// Mitsubishi GX Works2 project: L系列PLC与BD45XX通信例程20170617   PLC: L02

PROGRAM MAIN
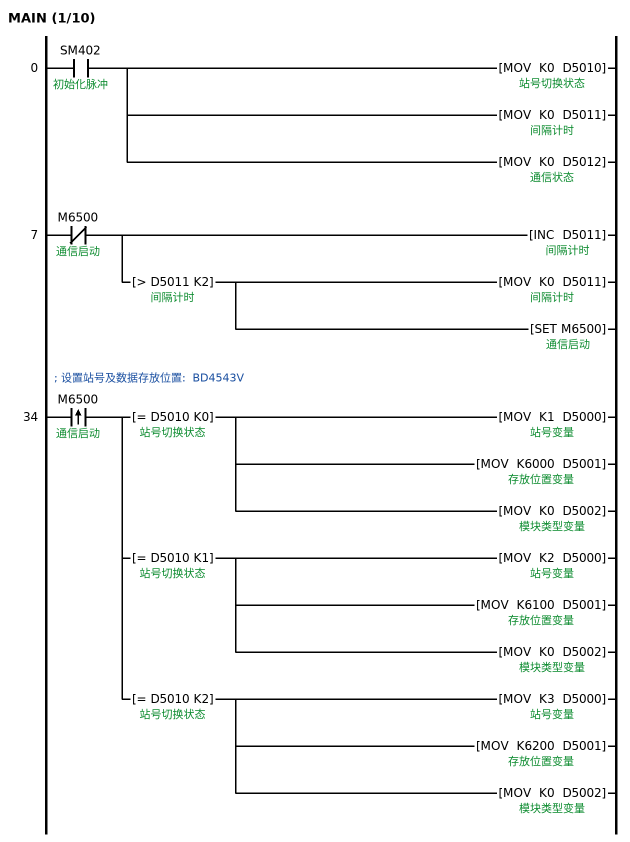
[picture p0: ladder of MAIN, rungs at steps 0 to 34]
0     LD      SM402  ; 初始化脉冲
      MOV     K0 D5010  ; 站号切换状态
      MOV     K0 D5011  ; 间隔计时
      MOV     K0 D5012  ; 通信状态
7     LDI     M6500  ; 通信启动
      INC     D5011
      AND>    D5011 K2  ; 间隔计时
      MOV     K0 D5011
      SET     M6500  ; 通信启动
; 设置站号及数据存放位置:  BD4543V
34    LDP     M6500  ; 通信启动
      MPS
      AND=    D5010 K0  ; 站号切换状态
      MOV     K1 D5000  ; 站号变量
      MOV     K6000 D5001  ; 存放位置变量
      MOV     K0 D5002  ; 模块类型变量
      MRD
      AND=    D5010 K1  ; 站号切换状态
      MOV     K2 D5000
      MOV     K6100 D5001
      MOV     K0 D5002
      MPP
      AND=    D5010 K2  ; 站号切换状态
      MOV     K3 D5000
      MOV     K6200 D5001
      MOV     K0 D5002
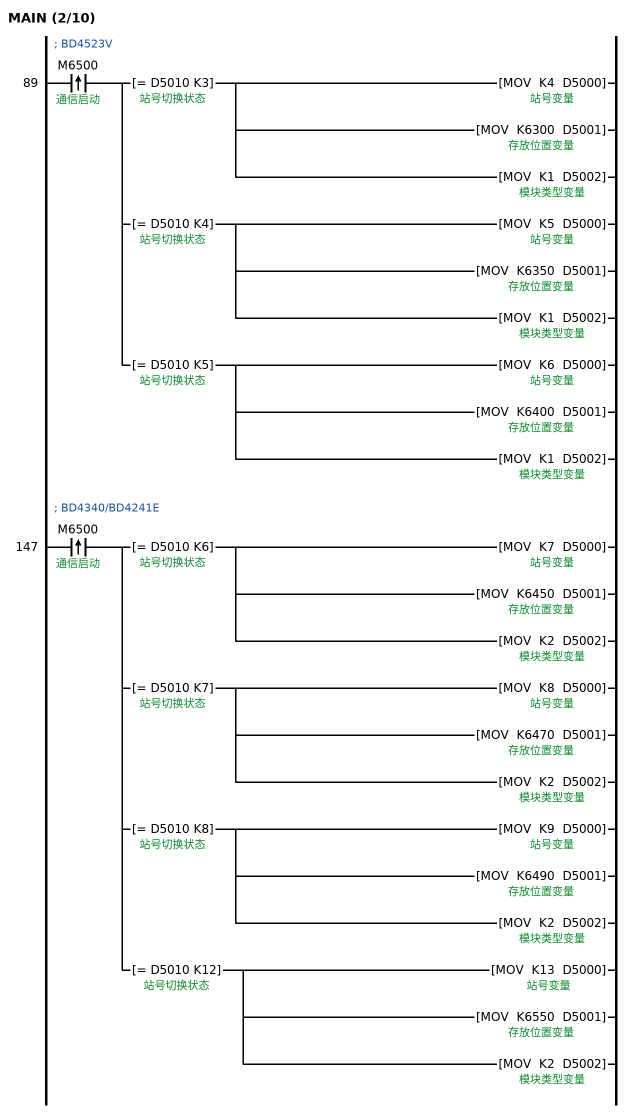
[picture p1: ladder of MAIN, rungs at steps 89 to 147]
; BD4523V
89    LDP     M6500  ; 通信启动
      MPS
      AND=    D5010 K3  ; 站号切换状态
      MOV     K4 D5000
      MOV     K6300 D5001
      MOV     K1 D5002
      MRD
      AND=    D5010 K4  ; 站号切换状态
      MOV     K5 D5000
      MOV     K6350 D5001
      MOV     K1 D5002
      MPP
      AND=    D5010 K5  ; 站号切换状态
      MOV     K6 D5000
      MOV     K6400 D5001
      MOV     K1 D5002
; BD4340/BD4241E
147   LDP     M6500  ; 通信启动
      MPS
      AND=    D5010 K6  ; 站号切换状态
      MOV     K7 D5000
      MOV     K6450 D5001
      MOV     K2 D5002
      MRD
      AND=    D5010 K7  ; 站号切换状态
      MOV     K8 D5000
      MOV     K6470 D5001
      MOV     K2 D5002
      MRD
      AND=    D5010 K8  ; 站号切换状态
      MOV     K9 D5000
      MOV     K6490 D5001
      MOV     K2 D5002
      MPP
      AND=    D5010 K12  ; 站号切换状态
      MOV     K13 D5000
      MOV     K6550 D5001
      MOV     K2 D5002
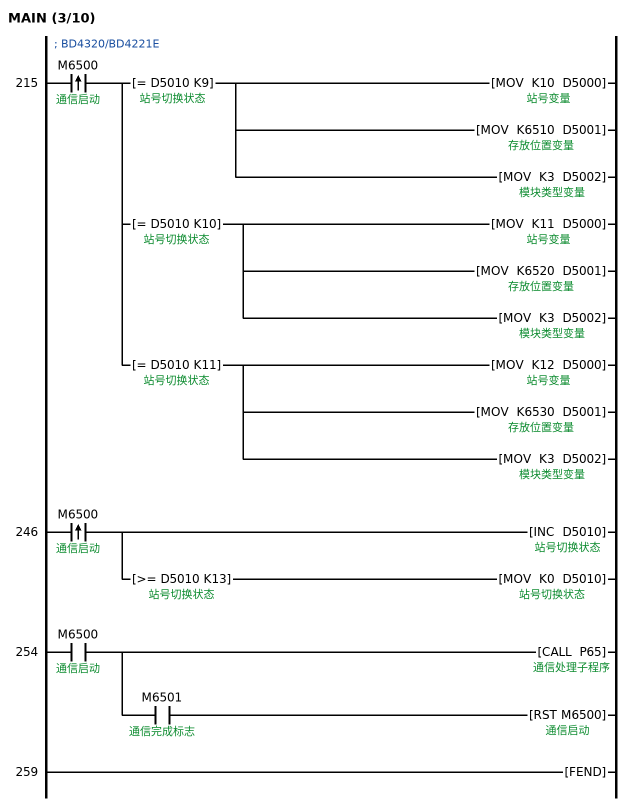
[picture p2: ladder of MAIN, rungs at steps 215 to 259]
; BD4320/BD4221E
215   LDP     M6500  ; 通信启动
      MPS
      AND=    D5010 K9  ; 站号切换状态
      MOV     K10 D5000
      MOV     K6510 D5001
      MOV     K3 D5002
      MRD
      AND=    D5010 K10  ; 站号切换状态
      MOV     K11 D5000
      MOV     K6520 D5001
      MOV     K3 D5002
      MPP
      AND=    D5010 K11  ; 站号切换状态
      MOV     K12 D5000
      MOV     K6530 D5001
      MOV     K3 D5002
246   LDP     M6500  ; 通信启动
      INC     D5010
      AND>=   D5010 K13  ; 站号切换状态
      MOV     K0 D5010
254   LD      M6500  ; 通信启动
      CALL    P65  ; 通信处理子程序
      AND     M6501  ; 通信完成标志
      RST     M6500  ; 通信启动
259   FEND
      P65
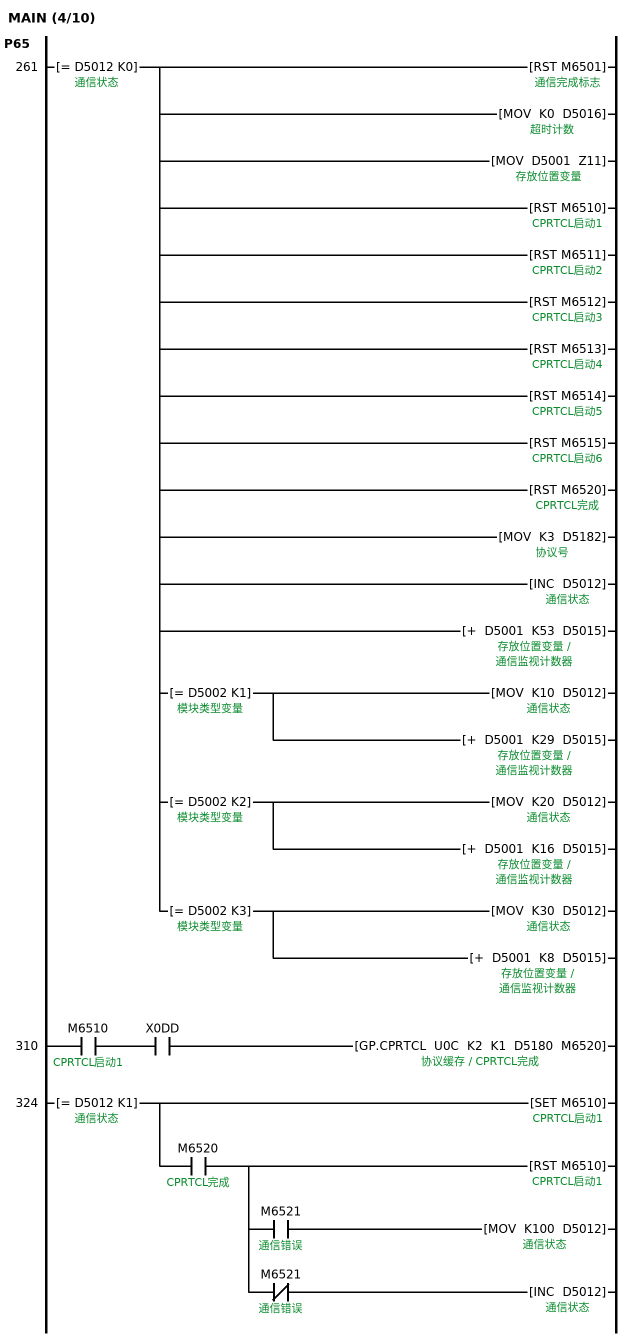
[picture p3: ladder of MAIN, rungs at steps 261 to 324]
261   LD=     D5012 K0  ; 通信状态
      RST     M6501  ; 通信完成标志
      MOV     K0 D5016  ; 超时计数
      MOV     D5001 Z11
      RST     M6510  ; CPRTCL启动1
      RST     M6511  ; CPRTCL启动2
      RST     M6512  ; CPRTCL启动3
      RST     M6513  ; CPRTCL启动4
      RST     M6514  ; CPRTCL启动5
      RST     M6515  ; CPRTCL启动6
      RST     M6520  ; CPRTCL完成
      MOV     K3 D5182  ; 协议号
      INC     D5012
      +       D5001 K53 D5015  ; 通信监视计数器
      MPS
      AND=    D5002 K1  ; 模块类型变量
      MOV     K10 D5012
      +       D5001 K29 D5015
      MRD
      AND=    D5002 K2  ; 模块类型变量
      MOV     K20 D5012
      +       D5001 K16 D5015
      MPP
      AND=    D5002 K3  ; 模块类型变量
      MOV     K30 D5012
      +       D5001 K8 D5015
310   LD      M6510  ; CPRTCL启动1
      AND     X0DD
      GP.CPRTCL U0C K2 K1 D5180 M6520  ; 协议缓存
324   LD=     D5012 K1  ; 通信状态
      SET     M6510  ; CPRTCL启动1
      AND     M6520  ; CPRTCL完成
      RST     M6510  ; CPRTCL启动1
      MPS
      AND     M6521  ; 通信错误
      MOV     K100 D5012
      MPP
      ANI     M6521  ; 通信错误
      INC     D5012
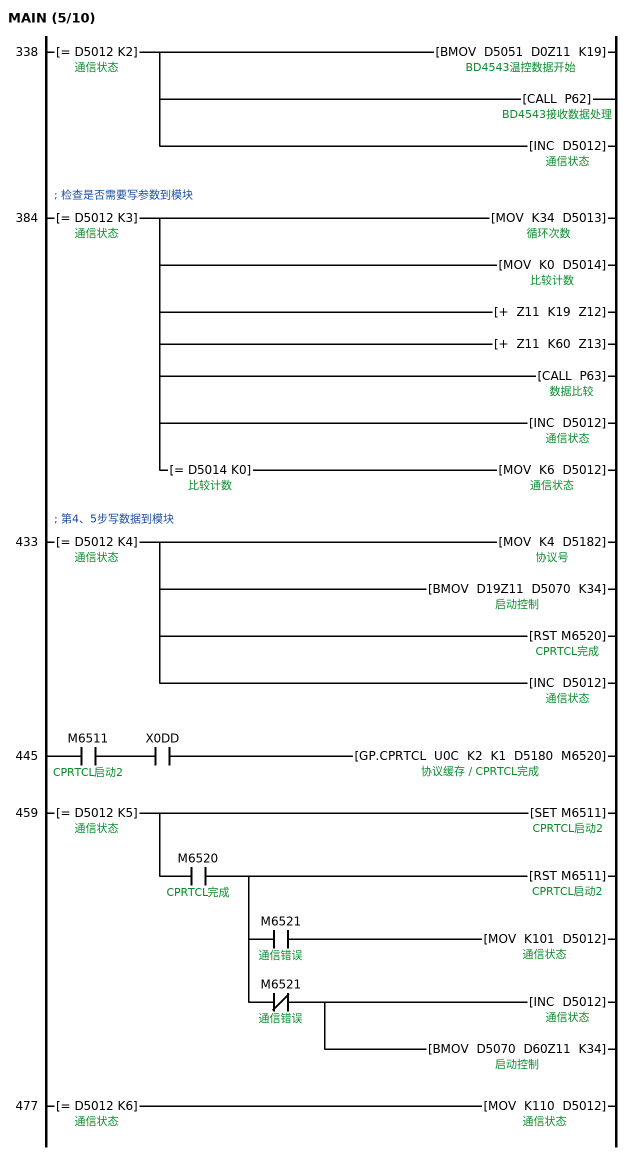
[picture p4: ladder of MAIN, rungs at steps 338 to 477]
338   LD=     D5012 K2  ; 通信状态
      BMOV    D5051 D0Z11 K19  ; BD4543温控数据开始
        [note] 数据处理
      CALL    P62  ; BD4543接收数据处理
      INC     D5012
; 检查是否需要写参数到模块
384   LD=     D5012 K3  ; 通信状态
      MOV     K34 D5013  ; 循环次数
      MOV     K0 D5014  ; 比较计数
      +       Z11 K19 Z12
      +       Z11 K60 Z13
      CALL    P63  ; 数据比较
      INC     D5012
      AND=    D5014 K0  ; 比较计数
      MOV     K6 D5012
; 第4、5步写数据到模块
433   LD=     D5012 K4  ; 通信状态
      MOV     K4 D5182
      BMOV    D19Z11 D5070 K34  ; 启动控制
      RST     M6520  ; CPRTCL完成
      INC     D5012
445   LD      M6511  ; CPRTCL启动2
      AND     X0DD
      GP.CPRTCL U0C K2 K1 D5180 M6520
459   LD=     D5012 K5  ; 通信状态
      SET     M6511  ; CPRTCL启动2
      AND     M6520  ; CPRTCL完成
      RST     M6511  ; CPRTCL启动2
      MPS
      AND     M6521  ; 通信错误
      MOV     K101 D5012
      MPP
      ANI     M6521  ; 通信错误
      INC     D5012
      BMOV    D5070 D60Z11 K34
477   LD=     D5012 K6  ; 通信状态
      MOV     K110 D5012
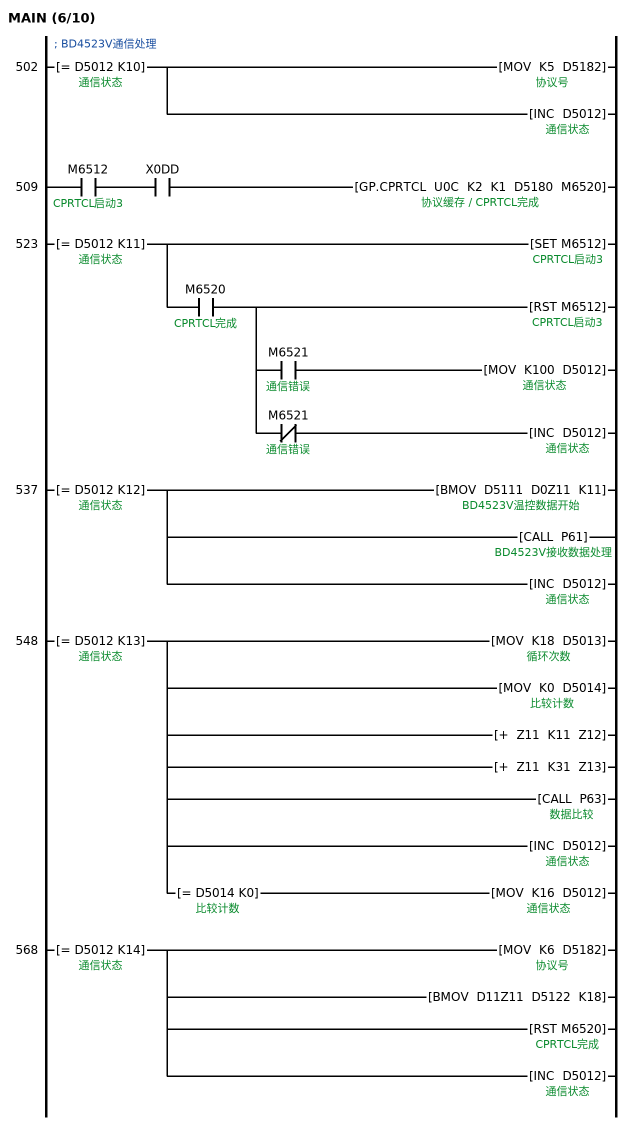
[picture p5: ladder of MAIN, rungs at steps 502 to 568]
; BD4523V通信处理
502   LD=     D5012 K10  ; 通信状态
      MOV     K5 D5182
      INC     D5012
509   LD      M6512  ; CPRTCL启动3
      AND     X0DD
      GP.CPRTCL U0C K2 K1 D5180 M6520
523   LD=     D5012 K11  ; 通信状态
      SET     M6512  ; CPRTCL启动3
      AND     M6520  ; CPRTCL完成
      RST     M6512  ; CPRTCL启动3
      MPS
      AND     M6521  ; 通信错误
      MOV     K100 D5012
      MPP
      ANI     M6521  ; 通信错误
      INC     D5012
537   LD=     D5012 K12  ; 通信状态
      BMOV    D5111 D0Z11 K11  ; BD4523V温控数据开始
      CALL    P61  ; BD4523V接收数据处理
      INC     D5012
548   LD=     D5012 K13  ; 通信状态
      MOV     K18 D5013
      MOV     K0 D5014
      +       Z11 K11 Z12
      +       Z11 K31 Z13
      CALL    P63
      INC     D5012
      AND=    D5014 K0  ; 比较计数
      MOV     K16 D5012
568   LD=     D5012 K14  ; 通信状态
      MOV     K6 D5182
      BMOV    D11Z11 D5122 K18
      RST     M6520  ; CPRTCL完成
      INC     D5012
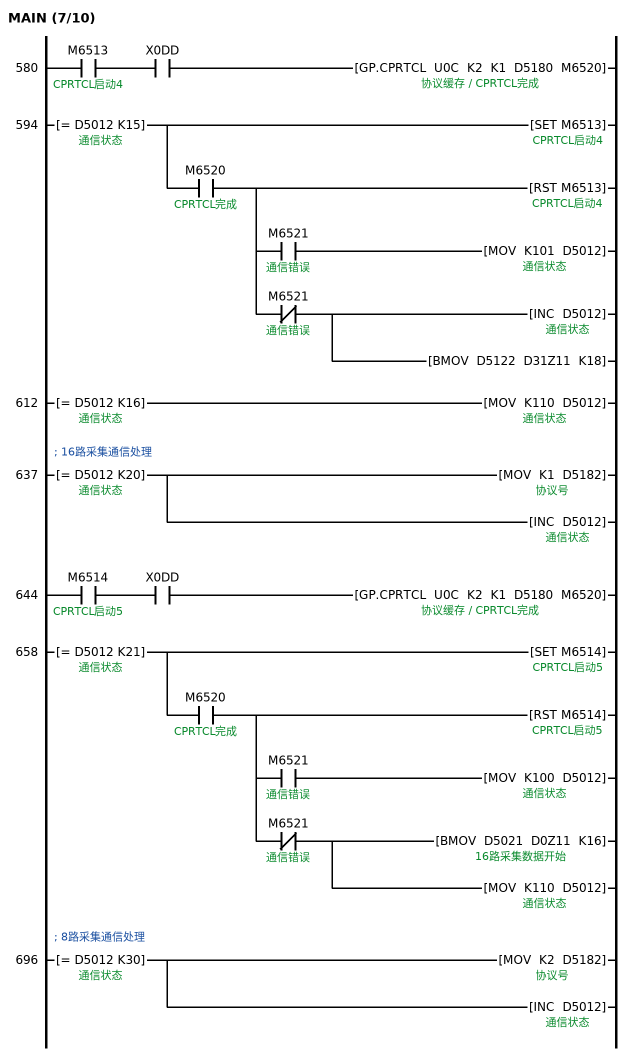
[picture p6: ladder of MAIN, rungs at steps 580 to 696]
580   LD      M6513  ; CPRTCL启动4
      AND     X0DD
      GP.CPRTCL U0C K2 K1 D5180 M6520
594   LD=     D5012 K15  ; 通信状态
      SET     M6513  ; CPRTCL启动4
      AND     M6520  ; CPRTCL完成
      RST     M6513  ; CPRTCL启动4
      MPS
      AND     M6521  ; 通信错误
      MOV     K101 D5012
      MPP
      ANI     M6521  ; 通信错误
      INC     D5012
      BMOV    D5122 D31Z11 K18
612   LD=     D5012 K16  ; 通信状态
      MOV     K110 D5012
; 16路采集通信处理
637   LD=     D5012 K20  ; 通信状态
      MOV     K1 D5182
      INC     D5012
644   LD      M6514  ; CPRTCL启动5
      AND     X0DD
      GP.CPRTCL U0C K2 K1 D5180 M6520
658   LD=     D5012 K21  ; 通信状态
      SET     M6514  ; CPRTCL启动5
      AND     M6520  ; CPRTCL完成
      RST     M6514  ; CPRTCL启动5
      MPS
      AND     M6521  ; 通信错误
      MOV     K100 D5012
      MPP
      ANI     M6521  ; 通信错误
      BMOV    D5021 D0Z11 K16  ; 16路采集数据开始
      MOV     K110 D5012
; 8路采集通信处理
696   LD=     D5012 K30  ; 通信状态
      MOV     K2 D5182
      INC     D5012
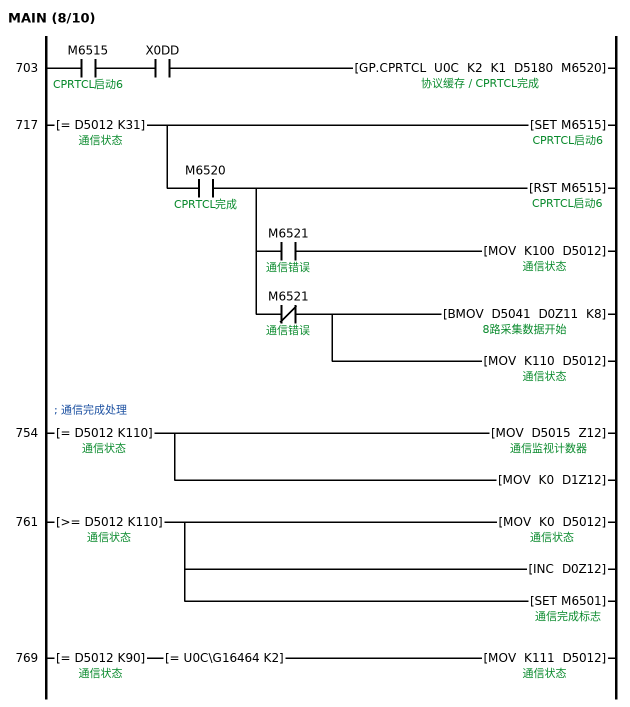
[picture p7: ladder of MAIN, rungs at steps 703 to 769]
703   LD      M6515  ; CPRTCL启动6
      AND     X0DD
      GP.CPRTCL U0C K2 K1 D5180 M6520
717   LD=     D5012 K31  ; 通信状态
      SET     M6515  ; CPRTCL启动6
      AND     M6520  ; CPRTCL完成
      RST     M6515  ; CPRTCL启动6
      MPS
      AND     M6521  ; 通信错误
      MOV     K100 D5012
      MPP
      ANI     M6521  ; 通信错误
      BMOV    D5041 D0Z11 K8  ; 8路采集数据开始
      MOV     K110 D5012
; 通信完成处理
754   LD=     D5012 K110  ; 通信状态
      MOV     D5015 Z12
      MOV     K0 D1Z12
761   LD>=    D5012 K110  ; 通信状态
      MOV     K0 D5012
      INC     D0Z12
      SET     M6501  ; 通信完成标志
769   LD=     D5012 K90  ; 通信状态
      AND=    U0C\G16464 K2
      MOV     K111 D5012
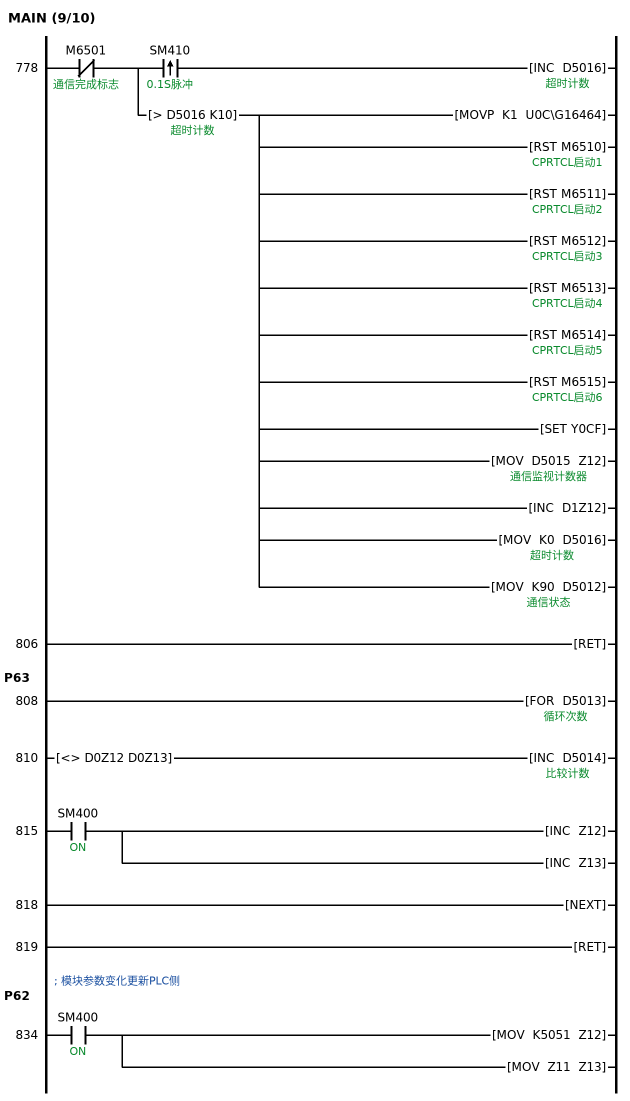
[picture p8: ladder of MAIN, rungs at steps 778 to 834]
778   LDI     M6501  ; 通信完成标志
      MPS
      ANDP    SM410  ; 0.1S脉冲
      INC     D5016
      MPP
      AND>    D5016 K10  ; 超时计数
      MOVP    K1 U0C\G16464
      RST     M6510  ; CPRTCL启动1
      RST     M6511  ; CPRTCL启动2
      RST     M6512  ; CPRTCL启动3
      RST     M6513  ; CPRTCL启动4
      RST     M6514  ; CPRTCL启动5
      RST     M6515  ; CPRTCL启动6
      SET     Y0CF
      MOV     D5015 Z12
      INC     D1Z12
      MOV     K0 D5016
      MOV     K90 D5012
806   RET
      P63
808   FOR     D5013
810   LD<>    D0Z12 D0Z13
      INC     D5014
815   LD      SM400  ; ON
      INC     Z12
      INC     Z13
818   NEXT
819   RET
; 模块参数变化更新PLC侧
      P62
834   LD      SM400  ; ON
      MOV     K5051 Z12
      MOV     Z11 Z13
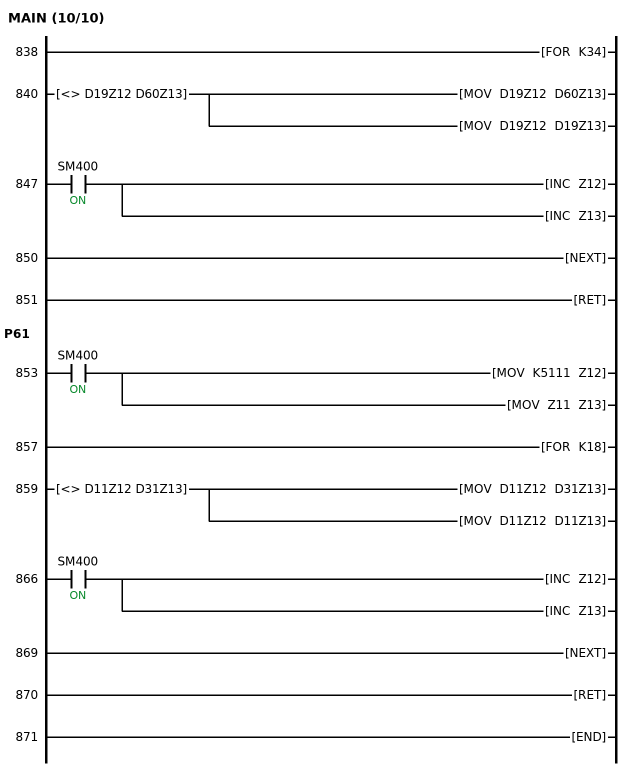
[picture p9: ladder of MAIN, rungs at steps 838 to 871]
838   FOR     K34
840   LD<>    D19Z12 D60Z13
      MOV     D19Z12 D60Z13
      MOV     D19Z12 D19Z13
847   LD      SM400  ; ON
      INC     Z12
      INC     Z13
850   NEXT
851   RET
      P61
853   LD      SM400  ; ON
      MOV     K5111 Z12
      MOV     Z11 Z13
857   FOR     K18
859   LD<>    D11Z12 D31Z13
      MOV     D11Z12 D31Z13
      MOV     D11Z12 D11Z13
866   LD      SM400  ; ON
      INC     Z12
      INC     Z13
869   NEXT
870   RET
871   END
END_PROGRAM

// device comments not shown above
X2D  ; 协议准备完成
D48  ; 通信故障计数
M6516  ; CPRTCL启动7
M6517  ; CPRTCL启动8
Y0F  ; 出错清除
